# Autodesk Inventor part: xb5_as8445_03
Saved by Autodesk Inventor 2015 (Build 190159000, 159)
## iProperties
Created: 2018-04
Part Number: xb5_as8445_03
Checked By: TraceParts S.A.
Material: Generic
Catalog Web Link: www.traceparts.com
Document SubType Name: Modeling
Designer: TraceParts
Density: 1 g/cm^3
Appearance: Default
Company: TraceParts S.A.
Author: TraceParts
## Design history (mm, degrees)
feature "xb5_as8445_03.ipt"
body "Solid1"
